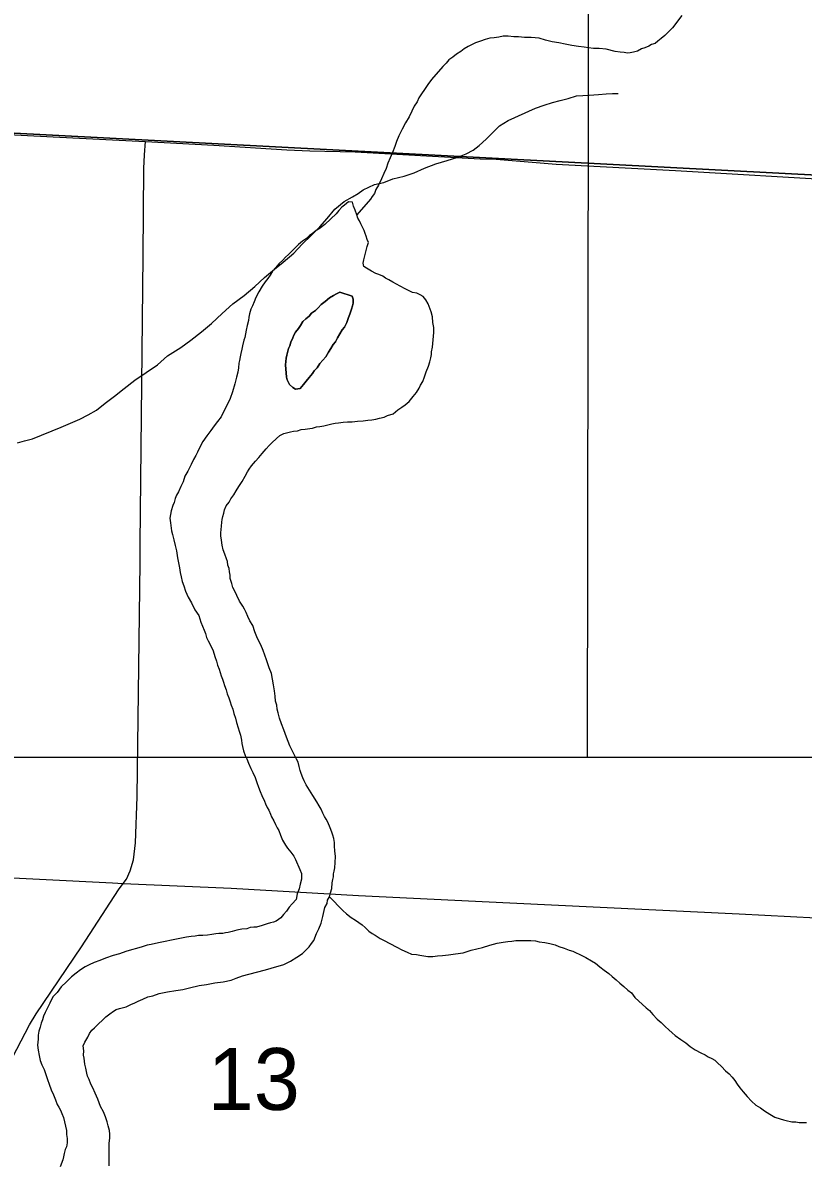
# Model space of a CAD drawing. Extents: x 0 to 68, y 0 to 52.9.
# Drawn here: x 43.238 to 43.796, y 32.478 to 33.293 of the extents above; entities that cross this region are included whole.
import ezdxf

# ---------------------------------------------------------------- set-up
doc = ezdxf.new("R2010")
doc.units = 0
for name, color, linetype in [('Default', 7, 'Continuous'), ('GM_X_County_Road', 7, 'Continuous'), ('GM_X_Minor_River', 7, 'Continuous')]:
    doc.layers.add(name, color=color, linetype=linetype)

msp = doc.modelspace()

# ---------------------------------------------------------------- linework, layer by layer
at = {"layer": 'Default'}
msp.add_line((41.10506, 32.7683), (50.34506, 32.7683), dxfattribs=at)
msp.add_lwpolyline([(43.64162, 32.7683), (43.64334, 34.0176), (43.64455, 34.6783), (43.65599, 35.34849), (43.66788, 36.0083), (43.67702, 36.44587), (43.68602, 36.84543), (43.69035, 37.04683), (43.69592, 37.28989), (43.69757, 37.31546), (43.70235, 37.35703), (43.70606, 37.38349), (43.71865, 37.45038), (43.791, 37.87267), (43.79415, 37.89545), (43.79589, 37.91564), (43.79763, 37.93547), (43.7985, 37.95966), (43.79937, 37.99098), (43.80146, 38.12323), (43.80732, 38.54108), (43.80967, 38.71924)], dxfattribs=at)
for points in [[(42.80414, 34.29415), (43.86565, 34.24064), (43.8561, 33.20575), (43.85578, 33.18135), (42.78551, 33.23738)], [(42.78551, 33.23738), (43.85578, 33.18135), (43.84389, 32.1529), (43.84313, 32.1253), (42.77036, 32.17257)]]:
    msp.add_lwpolyline(points, close=True, dxfattribs=at)
at = {"layer": 'GM_X_County_Road'}
for points in [[(42.79134, 33.23505), (42.82062, 33.23413), (42.9714, 33.2263), (43.25986, 33.21135), (43.32568, 33.20788)], [(43.30984, 32.67809), (43.31205, 32.68116), (43.31481, 32.68705), (43.31711, 32.695), (43.31864, 32.70704), (43.31982, 32.73991), (43.32196, 32.90735), (43.32196, 32.92038), (43.32408, 33.1263), (43.32455, 33.18864), (43.32513, 33.1985), (43.32568, 33.20788)], [(43.32568, 33.20788), (43.37455, 33.20531), (43.42674, 33.20193), (43.44315, 33.20142), (43.4756, 33.2005), (43.56491, 33.19564), (43.57622, 33.19536), (43.6192, 33.19169), (43.70447, 33.18737), (43.82571, 33.18021), (43.84872, 33.17948), (43.85871, 33.17916)], [(42.64392, 32.70706), (42.68084, 32.70646), (42.74934, 32.70549), (42.80509, 32.70371), (42.87046, 32.70063), (42.92292, 32.69787), (43.15494, 32.68593), (43.30214, 32.67845), (43.30984, 32.67809)], [(43.03806, 32.16233), (43.0418, 32.16982), (43.06085, 32.20791), (43.08652, 32.25719), (43.12967, 32.34203), (43.1418, 32.36716), (43.14274, 32.37037), (43.1716, 32.42838), (43.17938, 32.4431), (43.18984, 32.46545), (43.19193, 32.47025), (43.19426, 32.47812), (43.21008, 32.5133), (43.21485, 32.5225), (43.22184, 32.53677), (43.24285, 32.57703), (43.24761, 32.58479), (43.27991, 32.6328), (43.30651, 32.67348), (43.30984, 32.67809)], [(43.30984, 32.67809), (43.38699, 32.67455), (43.47796, 32.66953), (43.58607, 32.66416), (43.74995, 32.65639), (43.84168, 32.65147), (43.85052, 32.65099)]]:
    msp.add_lwpolyline(points, dxfattribs=at)
at = {"layer": 'GM_X_Minor_River'}
for points in [[(43.70888, 33.29793), (43.70237, 33.28916), (43.69912, 33.28598), (43.69669, 33.28359), (43.69425, 33.28161), (43.69182, 33.27962), (43.6898, 33.27804)], [(43.6898, 33.27804), (43.68738, 33.27726), (43.68536, 33.27607), (43.68253, 33.2749), (43.68011, 33.27412), (43.67728, 33.27254), (43.67446, 33.27177), (43.67205, 33.27139), (43.67003, 33.27101), (43.66763, 33.27144), (43.66482, 33.27187), (43.6612, 33.27231), (43.65479, 33.27398), (43.64997, 33.27443), (43.64595, 33.27448), (43.64234, 33.27491), (43.63913, 33.27535), (43.63511, 33.27579), (43.6303, 33.27665), (43.62548, 33.2775), (43.62107, 33.27835), (43.61625, 33.2792), (43.61144, 33.28046), (43.60703, 33.28171), (43.60141, 33.28217), (43.59659, 33.28222), (43.59217, 33.28267), (43.58896, 33.2827), (43.58494, 33.28315), (43.58132, 33.28319), (43.5781, 33.28242), (43.57488, 33.28205), (43.57166, 33.28168), (43.56844, 33.28091), (43.56521, 33.27974), (43.56158, 33.27857), (43.55875, 33.27699), (43.55633, 33.27581), (43.5535, 33.27423), (43.55107, 33.27225), (43.54783, 33.27027), (43.5454, 33.26829), (43.54257, 33.26631), (43.54054, 33.26392), (43.5381, 33.26153), (43.52997, 33.25237), (43.52753, 33.24878), (43.52508, 33.24519), (43.52304, 33.242), (43.521, 33.2392), (43.51977, 33.2364), (43.51773, 33.23321), (43.51608, 33.22961), (43.51403, 33.22561), (43.51158, 33.22122), (43.50913, 33.21682), (43.50667, 33.21203), (43.50502, 33.20802), (43.50378, 33.20442), (43.50213, 33.20002), (43.50048, 33.19642), (43.49884, 33.19242), (43.4976, 33.18881), (43.49595, 33.18521), (43.49431, 33.18121), (43.49225, 33.17681), (43.49021, 33.17362), (43.48938, 33.17081), (43.48775, 33.16882), (43.48653, 33.16683), (43.47677, 33.15567)], [(43.32627, 33.04291), (43.33436, 33.04836), (43.34146, 33.05481), (43.35107, 33.06074), (43.35816, 33.06619), (43.36575, 33.07214), (43.37284, 33.0781), (43.38045, 33.08505), (43.38806, 33.092), (43.39615, 33.09795), (43.40375, 33.1044), (43.41085, 33.11085), (43.41795, 33.11681), (43.42403, 33.12177), (43.43163, 33.12822), (43.43772, 33.13469), (43.44432, 33.14115), (43.4504, 33.14711), (43.45549, 33.15309), (43.46108, 33.15956), (43.46766, 33.16502), (43.47373, 33.16847), (43.47777, 33.17094), (43.48131, 33.17341), (43.48535, 33.17538), (43.48939, 33.17735), (43.49594, 33.17879), (43.50249, 33.18123), (43.51055, 33.18315), (43.51761, 33.18559), (43.52518, 33.18903), (43.53325, 33.19196), (43.54131, 33.19439), (43.54887, 33.19682), (43.55492, 33.19927), (43.55997, 33.20173), (43.56403, 33.2052), (43.5691, 33.20967), (43.57366, 33.21414), (43.57874, 33.21912), (43.58481, 33.22307), (43.60449, 33.23191), (43.61054, 33.23385), (43.61658, 33.2358), (43.62213, 33.23725), (43.62767, 33.2387), (43.63372, 33.24065), (43.64276, 33.24105), (43.6493, 33.24149), (43.65483, 33.24193), (43.65936, 33.24239), (43.66287, 33.24235), (43.66337, 33.24235)], [(43.48363, 33.11743), (43.48163, 33.11865), (43.48125, 33.12107), (43.48168, 33.12347), (43.48251, 33.12628), (43.48419, 33.13309), (43.48502, 33.1359), (43.48423, 33.13791), (43.48345, 33.14033), (43.48267, 33.14235), (43.48189, 33.14437), (43.4811, 33.14639), (43.47952, 33.14922), (43.47874, 33.15123), (43.47755, 33.15325), (43.47677, 33.15567), (43.4756, 33.1589), (43.47442, 33.16173), (43.47364, 33.16455), (43.47083, 33.16498), (43.468, 33.1626), (43.46597, 33.16101), (43.46394, 33.15862), (43.4619, 33.15623), (43.45825, 33.15265), (43.45379, 33.14868), (43.44974, 33.14551), (43.44772, 33.14432), (43.44488, 33.14194), (43.44286, 33.14076), (43.44083, 33.13877), (43.438, 33.13679), (43.43516, 33.13441), (43.43273, 33.13202), (43.43029, 33.12963), (43.42786, 33.12725), (43.42583, 33.12526), (43.4238, 33.12327), (43.42096, 33.12049), (43.41892, 33.1181), (43.41648, 33.11531), (43.41485, 33.11252), (43.41322, 33.11012), (43.41118, 33.10773), (43.40914, 33.10454), (43.40669, 33.10054), (43.40464, 33.09655), (43.40341, 33.09335), (43.40217, 33.09054), (43.40094, 33.08815), (43.40011, 33.08494), (43.39968, 33.08253), (43.39926, 33.08013), (43.39842, 33.07652), (43.39758, 33.07331), (43.39715, 33.0705), (43.39673, 33.0681), (43.3959, 33.0661), (43.39506, 33.06209), (43.39463, 33.05968), (43.3938, 33.05647), (43.39337, 33.05407), (43.39295, 33.05166), (43.39253, 33.04965), (43.39209, 33.04644), (43.39166, 33.04323), (43.39082, 33.03962), (43.38957, 33.03482), (43.3879, 33.02921), (43.38625, 33.0244), (43.37969, 33.01121), (43.37725, 33.00802), (43.3748, 33.00483), (43.37236, 33.00164), (43.36951, 32.99765), (43.36665, 32.99366), (43.3646, 32.98967), (43.36296, 32.98607), (43.36173, 32.98367), (43.3601, 32.98087), (43.35845, 32.97727), (43.35599, 32.97248), (43.35395, 32.96888), (43.3527, 32.96487), (43.35106, 32.96167), (43.34942, 32.95767), (43.34779, 32.95528), (43.34696, 32.95288), (43.34613, 32.95007), (43.3453, 32.94807), (43.34406, 32.94407), (43.34363, 32.94166), (43.3432, 32.93885), (43.34357, 32.93563), (43.34432, 32.93), (43.3451, 32.92718), (43.34587, 32.92355), (43.34703, 32.91952), (43.3478, 32.9155), (43.34855, 32.91066), (43.34932, 32.90704)], [(43.3843, 32.90788), (43.38351, 32.9099), (43.38234, 32.91313), (43.38117, 32.91635), (43.3804, 32.91958), (43.38003, 32.9232), (43.37966, 32.92642), (43.37968, 32.92842), (43.3797, 32.93084), (43.38013, 32.93324), (43.38016, 32.93605), (43.38058, 32.93806), (43.381, 32.94006), (43.38182, 32.94247), (43.38225, 32.94487), (43.38348, 32.94767), (43.38552, 32.95047), (43.38675, 32.95287), (43.38879, 32.95566), (43.39042, 32.95845), (43.39247, 32.96165), (43.39491, 32.96524), (43.39696, 32.96883), (43.3986, 32.97203), (43.39982, 32.97403), (43.40145, 32.97642), (43.4043, 32.97961), (43.40674, 32.98239), (43.40918, 32.98518), (43.41202, 32.98837), (43.41405, 32.99076), (43.41608, 32.99275), (43.41933, 32.99593), (43.42176, 32.99791), (43.42459, 32.99949), (43.42943, 33.00065), (43.43144, 33.00102), (43.43426, 33.0014), (43.43708, 33.00217), (43.43989, 33.00254), (43.44311, 33.00291), (43.44513, 33.00329), (43.44795, 33.00407), (43.45036, 33.00444), (43.45318, 33.00482), (43.456, 33.00559), (43.45882, 33.00637), (43.46124, 33.00674), (43.46365, 33.00712), (43.46687, 33.00749), (43.47009, 33.00786), (43.47331, 33.00782), (43.47733, 33.00818), (43.48135, 33.00854), (43.48457, 33.00891), (43.48739, 33.00928), (43.49021, 33.00966), (43.49303, 33.01043), (43.49625, 33.0112), (43.49868, 33.01238), (43.50271, 33.01355), (43.50595, 33.01632), (43.50878, 33.0183), (43.51121, 33.01989), (43.51405, 33.02227), (43.5169, 33.02585), (43.51933, 33.02864), (43.52138, 33.03184), (43.5222, 33.03384), (43.52383, 33.03663), (43.52507, 33.03984), (43.52631, 33.04344), (43.52796, 33.04744), (43.5288, 33.05065), (43.52963, 33.05345), (43.53005, 33.05586), (43.53007, 33.05787), (43.53091, 33.06107), (43.53181, 33.07151), (43.53185, 33.07513), (43.53108, 33.07875), (43.53072, 33.08278), (43.52995, 33.0864), (43.52838, 33.09003), (43.52759, 33.09205), (43.52601, 33.09488), (43.52403, 33.09731), (43.52203, 33.09854), (43.51963, 33.09977), (43.51642, 33.10021), (43.51402, 33.10144), (43.51122, 33.10267), (43.50762, 33.10472), (43.50242, 33.10759), (43.49963, 33.10922), (43.49723, 33.11045), (43.49523, 33.11168), (43.49243, 33.11291), (43.49043, 33.11374), (43.48723, 33.11538), (43.48363, 33.11743)], [(43.47339, 33.09744), (43.46457, 33.10034), (43.46215, 33.09916), (43.46013, 33.09798), (43.4573, 33.0964), (43.45405, 33.09362), (43.45122, 33.09164), (43.44919, 33.08925), (43.44716, 33.08726), (43.44433, 33.08528), (43.4427, 33.08329), (43.44027, 33.08131), (43.43824, 33.07932), (43.4366, 33.07652), (43.43498, 33.07453), (43.43294, 33.07174), (43.43171, 33.06974), (43.43089, 33.06774), (43.42965, 33.06454), (43.42882, 33.06214), (43.428, 33.06014), (43.42675, 33.05533), (43.42632, 33.05332), (43.4259, 33.05091), (43.42588, 33.0485), (43.42659, 33.03965), (43.42697, 33.03764), (43.42855, 33.03441), (43.43094, 33.03238)], [(43.47339, 33.09744), (43.47417, 33.09542), (43.47414, 33.09261), (43.47372, 33.0906), (43.47289, 33.0882), (43.47165, 33.0846), (43.47082, 33.08219), (43.46958, 33.07859), (43.46794, 33.07539), (43.46631, 33.0734), (43.46468, 33.0706), (43.46304, 33.06781), (43.46141, 33.06501), (43.45978, 33.06302), (43.45815, 33.06022), (43.45651, 33.05743), (43.45447, 33.05423), (43.45244, 33.05184), (43.4504, 33.04945), (43.44836, 33.04626), (43.44633, 33.04427), (43.44511, 33.04227), (43.44267, 33.03949), (43.44063, 33.0367), (43.4386, 33.03431), (43.43616, 33.03152), (43.43294, 33.03115), (43.43094, 33.03238), (43.42855, 33.03441), (43.42697, 33.03764), (43.42659, 33.03965), (43.42588, 33.0485), (43.4259, 33.05091), (43.42632, 33.05332), (43.42675, 33.05533), (43.428, 33.06014), (43.42882, 33.06214), (43.42965, 33.06454), (43.43089, 33.06774), (43.43171, 33.06974), (43.43294, 33.07174), (43.43498, 33.07453), (43.4366, 33.07652), (43.43824, 33.07932), (43.44027, 33.08131), (43.4427, 33.08329), (43.44433, 33.08528), (43.44716, 33.08726), (43.44919, 33.08925), (43.45122, 33.09164), (43.45405, 33.09362), (43.4573, 33.0964), (43.46013, 33.09798), (43.46215, 33.09916), (43.46457, 33.10034), (43.47339, 33.09744)], [(43.43094, 33.03238), (43.43294, 33.03115), (43.43616, 33.03152), (43.4386, 33.03431), (43.44063, 33.0367), (43.44267, 33.03949), (43.44511, 33.04227), (43.44633, 33.04427), (43.44836, 33.04626), (43.4504, 33.04945), (43.45244, 33.05184), (43.45447, 33.05423), (43.45651, 33.05743), (43.45815, 33.06022), (43.45978, 33.06302), (43.46141, 33.06501), (43.46304, 33.06781), (43.46468, 33.0706), (43.46631, 33.0734), (43.46794, 33.07539), (43.46958, 33.07859), (43.47082, 33.08219), (43.47165, 33.0846), (43.47289, 33.0882), (43.47372, 33.0906), (43.47414, 33.09261), (43.47417, 33.09542), (43.47339, 33.09744)], [(43.23433, 32.99264), (43.23937, 32.99409), (43.24491, 32.99554), (43.26559, 33.00386), (43.27215, 33.00681), (43.27871, 33.00975), (43.28477, 33.01271), (43.29084, 33.01616), (43.29691, 33.02112), (43.30349, 33.02607), (43.31058, 33.03152), (43.31818, 33.03747), (43.32627, 33.04291)], [(43.34932, 32.90704), (43.35009, 32.90341), (43.35046, 32.9002), (43.35123, 32.89697), (43.352, 32.89375), (43.35318, 32.89052), (43.35435, 32.88689), (43.35631, 32.88245), (43.35869, 32.87841), (43.36105, 32.87356), (43.36382, 32.86952), (43.36538, 32.86468), (43.36656, 32.86185), (43.36774, 32.85903), (43.36852, 32.85661), (43.3693, 32.85379), (43.37048, 32.85136), (43.37245, 32.84772), (43.37402, 32.84409), (43.37519, 32.84006), (43.37637, 32.83683), (43.37714, 32.83401), (43.37832, 32.83119), (43.3791, 32.82877), (43.37988, 32.82635), (43.38066, 32.82393), (43.38144, 32.82191), (43.38222, 32.81949), (43.3834, 32.81627), (43.38417, 32.81344), (43.38535, 32.81062), (43.38613, 32.8078), (43.38691, 32.80538), (43.38809, 32.80255), (43.38886, 32.79933), (43.39003, 32.7961), (43.3908, 32.79288), (43.39197, 32.78925), (43.39275, 32.78683), (43.39353, 32.78401), (43.3943, 32.78039), (43.39468, 32.77797), (43.39506, 32.77596), (43.39583, 32.77273), (43.397, 32.76951), (43.39819, 32.76708), (43.39936, 32.76386), (43.40093, 32.76022), (43.40251, 32.75739), (43.40408, 32.75376), (43.40525, 32.75013), (43.40643, 32.74691), (43.4076, 32.74368), (43.40878, 32.74085), (43.41075, 32.73681), (43.41154, 32.73479), (43.41272, 32.73237), (43.4139, 32.73035), (43.41508, 32.72753), (43.41587, 32.72551), (43.41745, 32.72268), (43.41863, 32.72025), (43.41981, 32.71783), (43.42099, 32.71581), (43.42217, 32.71258), (43.42374, 32.70895), (43.42571, 32.70531), (43.4273, 32.70329), (43.42969, 32.70045), (43.43167, 32.69761), (43.43285, 32.69519), (43.43599, 32.68792), (43.43717, 32.6851), (43.43715, 32.68309), (43.43713, 32.68108), (43.43629, 32.67747), (43.43546, 32.67427), (43.43422, 32.67066), (43.43337, 32.66665), (43.43053, 32.66347), (43.42849, 32.66108), (43.42646, 32.65829), (43.42443, 32.6559), (43.42239, 32.6535), (43.41915, 32.65113), (43.41714, 32.65035), (43.41512, 32.64996), (43.4127, 32.64919), (43.40907, 32.64802), (43.40504, 32.64685), (43.40303, 32.64688), (43.40062, 32.6465), (43.3982, 32.64572), (43.39458, 32.64536), (43.39095, 32.64459), (43.38773, 32.64382), (43.38491, 32.64305), (43.38289, 32.64266), (43.38088, 32.64228), (43.37807, 32.64231), (43.37605, 32.64193)], [(43.35719, 32.60355), (43.36403, 32.60509), (43.36927, 32.60583), (43.37531, 32.60698), (43.38134, 32.60772), (43.38698, 32.60887), (43.39061, 32.61044), (43.39505, 32.612), (43.39948, 32.61316), (43.41157, 32.61625), (43.4156, 32.61741), (43.41802, 32.61819), (43.42044, 32.61896), (43.42447, 32.62013), (43.42932, 32.62249), (43.43377, 32.62526), (43.43782, 32.62803), (43.44066, 32.63081), (43.44269, 32.6328), (43.44432, 32.63519), (43.44595, 32.63718), (43.44801, 32.64239), (43.44965, 32.64559), (43.45129, 32.64959), (43.45255, 32.6544), (43.45339, 32.65881), (43.45382, 32.66081), (43.45545, 32.66361), (43.45588, 32.66602), (43.4571, 32.66842), (43.45794, 32.67122), (43.45877, 32.67442), (43.45921, 32.67844), (43.45964, 32.68085), (43.46006, 32.68285), (43.46008, 32.68486), (43.4605, 32.68686), (43.46093, 32.68927), (43.46136, 32.69288), (43.46141, 32.6973), (43.46105, 32.70133), (43.46068, 32.70455), (43.4607, 32.70736), (43.46033, 32.71018), (43.45955, 32.71259), (43.45877, 32.71461), (43.45759, 32.71784), (43.45602, 32.72187), (43.45484, 32.7239), (43.45365, 32.72592), (43.45247, 32.72834), (43.45129, 32.73117), (43.44971, 32.73359), (43.44813, 32.73642), (43.44536, 32.74087), (43.44061, 32.74856), (43.43903, 32.75139), (43.43825, 32.7534), (43.43707, 32.75663), (43.43629, 32.75865), (43.43551, 32.76147), (43.43474, 32.76469), (43.43355, 32.76671), (43.43159, 32.77116), (43.42883, 32.77641), (43.42647, 32.78246), (43.42452, 32.78771), (43.42295, 32.79214), (43.42138, 32.79618), (43.42062, 32.7998), (43.41984, 32.80262), (43.41947, 32.80544), (43.41869, 32.80826), (43.41832, 32.81188), (43.41796, 32.8155), (43.4172, 32.81993), (43.41643, 32.82396), (43.41567, 32.82798), (43.4141, 32.83202), (43.41215, 32.83767), (43.4098, 32.84452), (43.40823, 32.84856), (43.40587, 32.853), (43.4039, 32.85784), (43.40234, 32.86228), (43.40036, 32.86552), (43.39879, 32.86875), (43.39761, 32.87157), (43.39643, 32.874), (43.39524, 32.87602), (43.39286, 32.87966), (43.39089, 32.8837), (43.38932, 32.88733), (43.38814, 32.88936), (43.38736, 32.89218), (43.38619, 32.89581), (43.38621, 32.89822), (43.38584, 32.90063), (43.38546, 32.90305), (43.38468, 32.90547), (43.3843, 32.90788)], [(43.4571, 32.66842), (43.46666, 32.65867), (43.46944, 32.65623), (43.47264, 32.65379), (43.47583, 32.65174), (43.47823, 32.65011), (43.48062, 32.64848), (43.48261, 32.64645), (43.4854, 32.64401), (43.4878, 32.64238), (43.4898, 32.64115), (43.49339, 32.6387), (43.49579, 32.63747), (43.50539, 32.63255), (43.50898, 32.6305), (43.51259, 32.62886), (43.51579, 32.62762), (43.5194, 32.62718), (43.52181, 32.62675), (43.52462, 32.62632), (43.52743, 32.62589), (43.53105, 32.62585), (43.53427, 32.62622), (43.53789, 32.62658), (43.54231, 32.62694), (43.54714, 32.62769), (43.55278, 32.62844), (43.55842, 32.63039), (43.56648, 32.63231), (43.57172, 32.63387), (43.57696, 32.63542), (43.58139, 32.63618), (43.58461, 32.63654), (43.58743, 32.63692), (43.59024, 32.63729), (43.59346, 32.63726), (43.59708, 32.63722), (43.6011, 32.63718), (43.60431, 32.63714), (43.60712, 32.63631), (43.61113, 32.63587), (43.61474, 32.63503), (43.61835, 32.63419), (43.62115, 32.63295), (43.62476, 32.63171), (43.62836, 32.63046), (43.63117, 32.62963), (43.63357, 32.6284), (43.63557, 32.62758), (43.63797, 32.62635), (43.64037, 32.62511), (43.64436, 32.62266), (43.64716, 32.62103), (43.65035, 32.61858), (43.65354, 32.61614), (43.65674, 32.61369), (43.65913, 32.61166), (43.66192, 32.60922), (43.66471, 32.60678), (43.6675, 32.60434), (43.67028, 32.6019), (43.67308, 32.59986), (43.67546, 32.59662), (43.68342, 32.5893), (43.68582, 32.58727), (43.6882, 32.58443), (43.69138, 32.58118), (43.69417, 32.57874), (43.69696, 32.5759), (43.69975, 32.57346), (43.70214, 32.57143), (43.70413, 32.5694), (43.70812, 32.56654), (43.71171, 32.56409), (43.71491, 32.56165), (43.7185, 32.5592), (43.7225, 32.55715), (43.7257, 32.55551), (43.7277, 32.55428), (43.7305, 32.55305), (43.73249, 32.55182), (43.73448, 32.54979), (43.73727, 32.54735), (43.74006, 32.54411), (43.74285, 32.54207), (43.74483, 32.53964), (43.74682, 32.5372), (43.7484, 32.53478), (43.75039, 32.53194), (43.75277, 32.5291), (43.75555, 32.52586), (43.75874, 32.52261), (43.76192, 32.51977), (43.76512, 32.51772), (43.76791, 32.51569), (43.77191, 32.51323), (43.7755, 32.51119), (43.77911, 32.50994), (43.78151, 32.50911), (43.78352, 32.50869), (43.78753, 32.50785)], [(43.37605, 32.64193), (43.37324, 32.64156), (43.37002, 32.64119), (43.3668, 32.64082), (43.36358, 32.64086), (43.36117, 32.64048), (43.35835, 32.64011), (43.35513, 32.63974), (43.35151, 32.63897), (43.34788, 32.63821), (43.3362, 32.63592), (43.33298, 32.63515), (43.32975, 32.63438), (43.32694, 32.634), (43.32331, 32.63284), (43.31928, 32.63167), (43.31565, 32.63051), (43.31162, 32.62934), (43.30718, 32.62778), (43.30275, 32.62662), (43.2971, 32.62467), (43.29307, 32.62311), (43.28903, 32.62154), (43.2854, 32.61997), (43.28257, 32.61839), (43.27933, 32.61642), (43.27609, 32.61404), (43.27285, 32.61126), (43.2692, 32.60768), (43.26555, 32.6041), (43.26269, 32.60011), (43.25945, 32.59693), (43.25739, 32.59253), (43.25616, 32.59014), (43.25494, 32.58774), (43.25411, 32.58574), (43.25288, 32.58334), (43.25205, 32.58053), (43.25122, 32.57813), (43.25039, 32.57533), (43.24956, 32.57252), (43.24913, 32.56971), (43.2491, 32.5669), (43.24866, 32.56249), (43.24902, 32.55886), (43.24979, 32.55524), (43.25056, 32.55162), (43.25173, 32.54839), (43.25331, 32.54516), (43.25448, 32.54153), (43.25565, 32.5379), (43.25682, 32.53467), (43.25839, 32.53064), (43.25996, 32.527), (43.26154, 32.52337), (43.26271, 32.52014), (43.2639, 32.51812), (43.26508, 32.5161), (43.26586, 32.51368), (43.26704, 32.51086), (43.26936, 32.50159), (43.26933, 32.49878), (43.26971, 32.49596), (43.26967, 32.49274), (43.26925, 32.48994), (43.26842, 32.48793), (43.26759, 32.48513), (43.26716, 32.48272), (43.26674, 32.48072), (43.26468, 32.47552)], [(43.29966, 32.47636), (43.29969, 32.47917), (43.29973, 32.48319), (43.29975, 32.486), (43.29978, 32.48881), (43.29982, 32.49243), (43.30026, 32.49604), (43.30028, 32.49885), (43.29991, 32.50167), (43.29914, 32.50489), (43.29836, 32.50772), (43.29719, 32.51135), (43.29562, 32.51498), (43.29365, 32.51861), (43.29169, 32.52386), (43.28972, 32.5283), (43.28815, 32.53193), (43.28657, 32.53476), (43.2854, 32.53799), (43.28421, 32.54041), (43.28383, 32.54243), (43.28306, 32.54605), (43.28229, 32.54887), (43.28193, 32.5533), (43.28155, 32.55531), (43.28158, 32.55853), (43.28121, 32.56215), (43.28244, 32.56455), (43.28449, 32.56814), (43.28572, 32.57094), (43.28735, 32.57333), (43.28938, 32.57492), (43.29222, 32.5777), (43.29506, 32.58049), (43.29749, 32.58287), (43.30033, 32.58485), (43.30276, 32.58684), (43.30478, 32.58802), (43.3072, 32.5888), (43.31203, 32.58996), (43.31527, 32.59153), (43.31809, 32.59271), (43.32051, 32.59388), (43.32374, 32.59546), (43.32738, 32.59703), (43.331, 32.59779), (43.33544, 32.59936), (43.34148, 32.6005), (43.34752, 32.60164), (43.35235, 32.60239), (43.35719, 32.60355)], [(43.78753, 32.50785), (43.79034, 32.50782), (43.79275, 32.50739), (43.79516, 32.50736), (43.79798, 32.50734)]]:
    msp.add_lwpolyline(points, dxfattribs=at)

# ---------------------------------------------------------------- texts
at = {"layer": 'Default'}
msp.add_text('13', height=0.0442, rotation=0.00001, dxfattribs=at).set_placement((43.37026, 32.51625))

doc.saveas('drawing.dxf')
